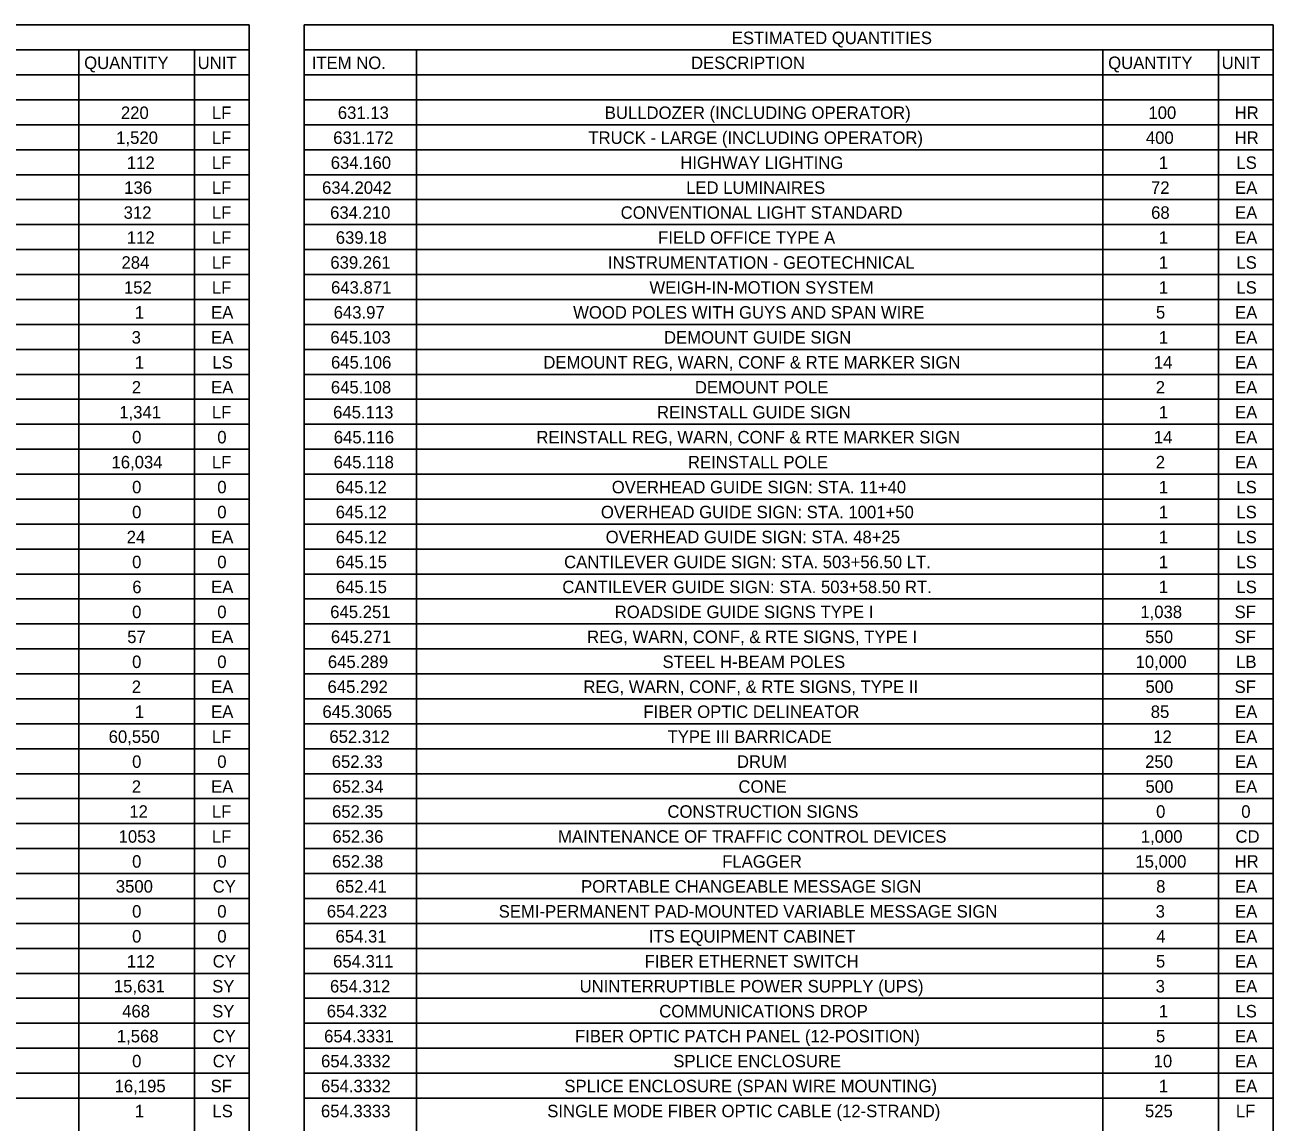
# Model space of a CAD drawing. Extents: x -18.7 to 5.6, y -2.7 to 5.1.
# Drawn here: x 4.632 to 5.617, y 0.886 to 1.751 of the extents above; entities that cross this region are included whole.
import ezdxf

# ---------------------------------------------------------------- set-up
doc = ezdxf.new("R2010")
doc.units = 0
doc.layers.add('ANNOTATION', color=7, linetype='Continuous')
doc.layers.add('BORDER', color=7, linetype='Continuous')

msp = doc.modelspace()

# ---------------------------------------------------------------- linework, layer by layer
at = {"layer": 'BORDER'}
for p, q in [((3.9448, 1.73155), (4.8091, 1.73155)), ((4.67472, 1.73155), (4.67472, 0.01886)), ((4.76611, 1.73155), (4.76611, 0.01886)), ((4.85265, 1.73155), (5.61696, 1.73155)), ((4.94124, 1.73155), (4.94124, 0.01886)), ((5.48258, 1.73155), (5.48258, 0.01886)), ((5.57397, 1.73155), (5.57397, 0.01886)), ((3.9448, 1.71186), (4.8091, 1.71186)), ((4.85265, 1.71186), (5.61696, 1.71186)), ((3.9448, 1.69217), (4.8091, 1.69217)), ((4.85265, 1.69217), (5.61696, 1.69217)), ((3.9448, 1.67249), (4.8091, 1.67249)), ((4.85265, 1.67249), (5.61696, 1.67249)), ((3.9448, 1.6528), (4.8091, 1.6528)), ((4.85265, 1.6528), (5.61696, 1.6528)), ((3.9448, 1.63312), (4.8091, 1.63312)), ((4.85265, 1.63312), (5.61696, 1.63312)), ((3.9448, 1.61343), (4.8091, 1.61343)), ((4.85265, 1.61343), (5.61696, 1.61343)), ((3.9448, 1.59374), (4.8091, 1.59374)), ((4.85265, 1.59374), (5.61696, 1.59374)), ((3.9448, 1.57406), (4.8091, 1.57406)), ((4.85265, 1.57406), (5.61696, 1.57406)), ((3.9448, 1.55437), (4.8091, 1.55437)), ((4.85265, 1.55437), (5.61696, 1.55437)), ((3.9448, 1.53469), (4.8091, 1.53469)), ((4.85265, 1.53469), (5.61696, 1.53469)), ((3.9448, 1.515), (4.8091, 1.515)), ((4.85265, 1.515), (5.61696, 1.515)), ((3.9448, 1.49531), (4.8091, 1.49531)), ((4.85265, 1.49531), (5.61696, 1.49531)), ((3.9448, 1.47563), (4.8091, 1.47563)), ((4.85265, 1.47563), (5.61696, 1.47563)), ((3.9448, 1.45594), (4.8091, 1.45594)), ((4.85265, 1.45594), (5.61696, 1.45594)), ((3.9448, 1.43626), (4.8091, 1.43626)), ((4.85265, 1.43626), (5.61696, 1.43626)), ((3.9448, 1.41657), (4.8091, 1.41657)), ((4.85265, 1.41657), (5.61696, 1.41657)), ((3.9448, 1.39688), (4.8091, 1.39688)), ((4.85265, 1.39688), (5.61696, 1.39688)), ((3.9448, 1.3772), (4.8091, 1.3772)), ((4.85265, 1.3772), (5.61696, 1.3772)), ((3.9448, 1.35751), (4.8091, 1.35751)), ((4.85265, 1.35751), (5.61696, 1.35751)), ((3.9448, 1.33783), (4.8091, 1.33783)), ((4.85265, 1.33783), (5.61696, 1.33783)), ((3.9448, 1.31814), (4.8091, 1.31814)), ((4.85265, 1.31814), (5.61696, 1.31814)), ((3.9448, 1.29845), (4.8091, 1.29845)), ((4.85265, 1.29845), (5.61696, 1.29845)), ((3.9448, 1.27877), (4.8091, 1.27877)), ((4.85265, 1.27877), (5.61696, 1.27877)), ((3.9448, 1.25908), (4.8091, 1.25908)), ((4.85265, 1.25908), (5.61696, 1.25908)), ((3.9448, 1.2394), (4.8091, 1.2394)), ((4.85265, 1.2394), (5.61696, 1.2394)), ((3.9448, 1.21971), (4.8091, 1.21971)), ((4.85265, 1.21971), (5.61696, 1.21971)), ((3.9448, 1.20002), (4.8091, 1.20002)), ((4.85265, 1.20002), (5.61696, 1.20002)), ((3.9448, 1.18034), (4.8091, 1.18034)), ((4.85265, 1.18034), (5.61696, 1.18034)), ((3.9448, 1.16065), (4.8091, 1.16065)), ((4.85265, 1.16065), (5.61696, 1.16065)), ((3.9448, 1.14097), (4.8091, 1.14097)), ((4.85265, 1.14097), (5.61696, 1.14097)), ((3.9448, 1.12128), (4.8091, 1.12128)), ((4.85265, 1.12128), (5.61696, 1.12128)), ((3.9448, 1.10159), (4.8091, 1.10159)), ((4.85265, 1.10159), (5.61696, 1.10159)), ((3.9448, 1.08191), (4.8091, 1.08191)), ((4.85265, 1.08191), (5.61696, 1.08191)), ((3.9448, 1.06222), (4.8091, 1.06222)), ((4.85265, 1.06222), (5.61696, 1.06222)), ((3.9448, 1.04254), (4.8091, 1.04254)), ((4.85265, 1.04254), (5.61696, 1.04254)), ((3.9448, 1.02285), (4.8091, 1.02285)), ((4.85265, 1.02285), (5.61696, 1.02285)), ((3.9448, 1.00316), (4.8091, 1.00316)), ((4.85265, 1.00316), (5.61696, 1.00316)), ((3.9448, 0.98348), (4.8091, 0.98348)), ((4.85265, 0.98348), (5.61696, 0.98348)), ((3.9448, 0.96379), (4.8091, 0.96379)), ((4.85265, 0.96379), (5.61696, 0.96379)), ((3.9448, 0.94411), (4.8091, 0.94411)), ((4.85265, 0.94411), (5.61696, 0.94411)), ((3.9448, 0.92442), (4.8091, 0.92442)), ((4.85265, 0.92442), (5.61696, 0.92442)), ((3.9448, 0.90473), (4.8091, 0.90473)), ((4.85265, 0.90473), (5.61696, 0.90473))]:
    msp.add_line(p, q, dxfattribs=at)
for points in [[(3.9448, 1.75123), (4.8091, 1.75123), (4.8091, 0.01886), (3.9448, 0.01886)], [(4.85265, 1.75123), (5.61696, 1.75123), (5.61696, 0.01886), (4.85265, 0.01886)]]:
    msp.add_lwpolyline(points, close=True, dxfattribs=at)

# ---------------------------------------------------------------- texts
at = {"layer": 'ANNOTATION'}
for s, height, p in [('220', 0.009843, (4.70801, 1.67708)), ('LF', 0.009843, (4.77978, 1.67708)), ('631.13', 0.009843, (4.87914, 1.67708)), ('BULLDOZER (INCLUDING OPERATOR)', 0.009843, (5.08976, 1.67708)), ('100', 0.009843, (5.51865, 1.67708)), ('HR', 0.009843, (5.58665, 1.67708)), ('1,520', 0.009843, (4.70429, 1.6574)), ('LF', 0.009843, (4.77978, 1.6574)), ('631.172', 0.009843, (4.8755, 1.6574)), ('TRUCK - LARGE (INCLUDING OPERATOR)', 0.009843, (5.0768, 1.6574)), ('400', 0.009843, (5.51664, 1.6574)), ('HR', 0.009843, (5.58665, 1.6574)), ('112', 0.009843, (4.7127, 1.63771)), ('LF', 0.009843, (4.77978, 1.63771)), ('634.160', 0.009843, (4.87353, 1.63771)), ('HIGHWAY LIGHTING', 0.009843, (5.14929, 1.63771)), ('1', 0.00984, (5.52687, 1.63771)), ('LS', 0.009843, (5.58806, 1.63771)), ('136', 0.009843, (4.71057, 1.61803)), ('LF', 0.009843, (4.77978, 1.61803)), ('634.2042', 0.009843, (4.86667, 1.61803)), ('LED LUMINAIRES', 0.009843, (5.15393, 1.61803)), ('72', 0.009843, (5.5207, 1.61803)), ('EA', 0.009843, (5.58701, 1.61803)), ('312', 0.009843, (4.71014, 1.59834)), ('LF', 0.009843, (4.77978, 1.59834)), ('634.210', 0.009843, (4.87306, 1.59834)), ('CONVENTIONAL LIGHT STANDARD', 0.009843, (5.10228, 1.59834)), ('68', 0.009843, (5.52078, 1.59834)), ('EA', 0.009843, (5.58701, 1.59834)), ('112', 0.009843, (4.7127, 1.57865)), ('LF', 0.009843, (4.77978, 1.57865)), ('639.18', 0.009843, (4.87752, 1.57865)), ('FIELD OFFICE TYPE A', 0.009843, (5.13182, 1.57865)), ('1', 0.00984, (5.52687, 1.57865)), ('EA', 0.009843, (5.58701, 1.57865)), ('284', 0.009843, (4.70847, 1.55897)), ('LF', 0.009843, (4.77978, 1.55897)), ('639.261', 0.009843, (4.87322, 1.55897)), ('INSTRUMENTATION - GEOTECHNICAL', 0.009843, (5.0922, 1.55897)), ('1', 0.00984, (5.52687, 1.55897)), ('LS', 0.009843, (5.58806, 1.55897)), ('152', 0.009843, (4.71037, 1.53928)), ('LF', 0.009843, (4.77978, 1.53928)), ('643.871', 0.009843, (4.87376, 1.53928)), ('WEIGH-IN-MOTION SYSTEM', 0.009843, (5.12498, 1.53928)), ('1', 0.00984, (5.52687, 1.53928)), ('LS', 0.009843, (5.58806, 1.53928)), ('1', 0.00984, (4.71901, 1.5196)), ('EA', 0.009843, (4.77916, 1.5196)), ('643.97', 0.009843, (4.87585, 1.5196)), ('WOOD POLES WITH GUYS AND SPAN WIRE', 0.009843, (5.06478, 1.5196)), ('5', 0.00984, (5.52458, 1.5196)), ('EA', 0.009843, (5.58701, 1.5196)), ('3', 0.00984, (4.71649, 1.49991)), ('EA', 0.009843, (4.77916, 1.49991)), ('645.103', 0.009843, (4.87325, 1.49991)), ('DEMOUNT GUIDE SIGN', 0.009843, (5.13644, 1.49991)), ('1', 0.00984, (5.52687, 1.49991)), ('EA', 0.009843, (5.58701, 1.49991)), ('1', 0.00984, (4.71901, 1.48022)), ('LS', 0.009843, (4.78021, 1.48022)), ('645.106', 0.009843, (4.87376, 1.48022)), ('DEMOUNT REG, WARN, CONF & RTE MARKER SIGN', 0.009843, (5.04127, 1.48022)), ('14', 0.009843, (5.52292, 1.48022)), ('EA', 0.009843, (5.58701, 1.48022)), ('2', 0.00984, (4.71657, 1.46054)), ('EA', 0.009843, (4.77916, 1.46054)), ('645.108', 0.009843, (4.87364, 1.46054)), ('DEMOUNT POLE', 0.009843, (5.1608, 1.46054)), ('2', 0.00984, (5.52442, 1.46054)), ('EA', 0.009843, (5.58701, 1.46054)), ('1,341', 0.009843, (4.7067, 1.44085)), ('LF', 0.009843, (4.77978, 1.44085)), ('645.113', 0.009843, (4.87542, 1.44085)), ('REINSTALL GUIDE SIGN', 0.009843, (5.13098, 1.44085)), ('1', 0.00984, (5.52687, 1.44085)), ('EA', 0.009843, (5.58701, 1.44085)), ('0', 0.00984, (4.71684, 1.42117)), ('0', 0.00984, (4.78404, 1.42117)), ('645.116', 0.009843, (4.87593, 1.42117)), ('REINSTALL REG, WARN, CONF & RTE MARKER SIGN', 0.009843, (5.03581, 1.42117)), ('14', 0.009843, (5.52292, 1.42117)), ('EA', 0.009843, (5.58701, 1.42117)), ('16,034', 0.009843, (4.70058, 1.40148)), ('LF', 0.009843, (4.77978, 1.40148)), ('645.118', 0.009843, (4.87581, 1.40148)), ('REINSTALL POLE', 0.009843, (5.15534, 1.40148)), ('2', 0.00984, (5.52442, 1.40148)), ('EA', 0.009843, (5.58701, 1.40148)), ('0', 0.00984, (4.71684, 1.38179)), ('0', 0.00984, (4.78404, 1.38179)), ('645.12', 0.009843, (4.87744, 1.38179)), ('OVERHEAD GUIDE SIGN: STA. 11+40', 0.009843, (5.09522, 1.38179)), ('1', 0.00984, (5.52687, 1.38179)), ('LS', 0.009843, (5.58806, 1.38179)), ('0', 0.00984, (4.71684, 1.36211)), ('0', 0.00984, (4.78404, 1.36211)), ('645.12', 0.009843, (4.87744, 1.36211)), ('OVERHEAD GUIDE SIGN: STA. 1001+50', 0.009843, (5.08669, 1.36211)), ('1', 0.00984, (5.52687, 1.36211)), ('LS', 0.009843, (5.58806, 1.36211)), ('24', 0.009843, (4.71258, 1.34242)), ('EA', 0.009843, (4.77916, 1.34242)), ('645.12', 0.009843, (4.87744, 1.34242)), ('OVERHEAD GUIDE SIGN: STA. 48+25', 0.009843, (5.09045, 1.34242)), ('1', 0.00984, (5.52687, 1.34242)), ('LS', 0.009843, (5.58806, 1.34242)), ('0', 0.00984, (4.71684, 1.32274)), ('0', 0.00984, (4.78404, 1.32274)), ('645.15', 0.009843, (4.87759, 1.32274)), ('CANTILEVER GUIDE SIGN: STA. 503+56.50 LT.', 0.009843, (5.05766, 1.32274)), ('1', 0.00984, (5.52687, 1.32274)), ('LS', 0.009843, (5.58806, 1.32274)), ('6', 0.00984, (4.71699, 1.30305)), ('EA', 0.009843, (4.77916, 1.30305)), ('645.15', 0.009843, (4.87759, 1.30305)), ('CANTILEVER GUIDE SIGN: STA. 503+58.50 RT.', 0.009843, (5.05626, 1.30305)), ('1', 0.00984, (5.52687, 1.30305)), ('LS', 0.009843, (5.58806, 1.30305)), ('0', 0.00984, (4.71684, 1.28336)), ('0', 0.00984, (4.78404, 1.28336)), ('645.251', 0.009843, (4.87314, 1.28336)), ('ROADSIDE GUIDE SIGNS TYPE I ', 0.009843, (5.0976, 1.28336)), ('1,038', 0.009843, (5.51227, 1.28336)), ('SF', 0.009843, (5.58663, 1.28336)), ('57', 0.009843, (4.71297, 1.26368)), ('EA', 0.009843, (4.77916, 1.26368)), ('645.271', 0.009843, (4.87368, 1.26368)), ('REG, WARN, CONF, & RTE SIGNS, TYPE I', 0.009843, (5.07581, 1.26368)), ('550', 0.009843, (5.51617, 1.26368)), ('SF', 0.009843, (5.58663, 1.26368)), ('0', 0.00984, (4.71684, 1.24399)), ('0', 0.00984, (4.78404, 1.24399)), ('645.289', 0.009843, (4.87128, 1.24399)), ('STEEL H-BEAM POLES', 0.009843, (5.1353, 1.24399)), ('10,000', 0.009843, (5.50851, 1.24399)), ('LB', 0.009843, (5.58783, 1.24399)), ('2', 0.00984, (4.71657, 1.22431)), ('EA', 0.009843, (4.77916, 1.22431)), ('645.292', 0.009843, (4.87101, 1.22431)), ('REG, WARN, CONF, & RTE SIGNS, TYPE II', 0.009843, (5.07289, 1.22431)), ('500', 0.009843, (5.51633, 1.22431)), ('SF', 0.009843, (5.58663, 1.22431)), ('1', 0.00984, (4.71901, 1.20462)), ('EA', 0.009843, (4.77916, 1.20462)), ('645.3065', 0.009843, (4.86698, 1.20462)), ('FIBER OPTIC DELINEATOR', 0.009843, (5.12024, 1.20462)), ('85', 0.009843, (5.52047, 1.20462)), ('EA', 0.009843, (5.58701, 1.20462)), ('60,550', 0.009843, (4.69833, 1.18493)), ('LF', 0.009843, (4.77978, 1.18493)), ('652.312', 0.009843, (4.87248, 1.18493)), ('TYPE III BARRICADE', 0.009843, (5.13927, 1.18493)), ('12', 0.009843, (5.52249, 1.18493)), ('EA', 0.009843, (5.58701, 1.18493)), ('0', 0.00984, (4.71684, 1.16525)), ('0', 0.00984, (4.78404, 1.16525)), ('652.33', 0.009843, (4.87434, 1.16525)), ('DRUM', 0.009843, (5.19401, 1.16525)), ('250', 0.009843, (5.51602, 1.16525)), ('EA', 0.009843, (5.58701, 1.16525)), ('2', 0.00984, (4.71657, 1.14556)), ('EA', 0.009843, (4.77916, 1.14556)), ('652.34', 0.009843, (4.87484, 1.14556)), ('CONE', 0.009843, (5.19524, 1.14556)), ('500', 0.009843, (5.51633, 1.14556)), ('EA', 0.009843, (5.58701, 1.14556)), ('12', 0.009843, (4.71463, 1.12588)), ('LF', 0.009843, (4.77978, 1.12588)), ('652.35', 0.009843, (4.87457, 1.12588)), ('CONSTRUCTION SIGNS', 0.009843, (5.13917, 1.12588)), ('0', 0.00984, (5.5247, 1.12588)), ('0', 0.00984, (5.5919, 1.12588)), ('1053', 0.009843, (4.70619, 1.10619)), ('LF', 0.009843, (4.77978, 1.10619)), ('652.36', 0.009843, (4.87484, 1.10619)), ('MAINTENANCE OF TRAFFIC CONTROL DEVICES', 0.009843, (5.05289, 1.10619)), ('1,000', 0.009843, (5.51262, 1.10619)), ('CD', 0.009843, (5.58733, 1.10619)), ('0', 0.00984, (4.71684, 1.0865)), ('0', 0.00984, (4.78404, 1.0865)), ('652.38', 0.009843, (4.87472, 1.0865)), ('FLAGGER', 0.009843, (5.18237, 1.0865)), ('15,000', 0.009843, (5.50835, 1.0865)), ('HR', 0.009843, (5.58665, 1.0865)), ('3500', 0.009843, (4.70398, 1.06682)), ('CY', 0.009843, (4.7804, 1.06682)), ('652.41', 0.009843, (4.8774, 1.06682)), ('PORTABLE CHANGEABLE MESSAGE SIGN', 0.009843, (5.07106, 1.06682)), ('8', 0.00984, (5.52474, 1.06682)), ('EA', 0.009843, (5.58701, 1.06682)), ('0', 0.00984, (4.71684, 1.04713)), ('0', 0.00984, (4.78404, 1.04713)), ('654.223', 0.009843, (4.87046, 1.04713)), ('SEMI-PERMANENT PAD-MOUNTED VARIABLE MESSAGE SIGN', 0.009843, (5.00605, 1.04713)), ('3', 0.00984, (5.52435, 1.04713)), ('EA', 0.009843, (5.58701, 1.04713)), ('0', 0.00984, (4.71684, 1.02745)), ('0', 0.00984, (4.78404, 1.02745)), ('654.31', 0.009843, (4.87732, 1.02745)), ('ITS EQUIPMENT CABINET', 0.009843, (5.12449, 1.02745)), ('4', 0.00984, (5.52485, 1.02745)), ('EA', 0.009843, (5.58701, 1.02745)), ('112', 0.009843, (4.7127, 1.00776)), ('CY', 0.009843, (4.7804, 1.00776)), ('654.311', 0.009843, (4.87539, 1.00776)), ('FIBER ETHERNET SWITCH', 0.009843, (5.12116, 1.00776)), ('5', 0.00984, (5.52458, 1.00776)), ('EA', 0.009843, (5.58701, 1.00776)), ('15,631', 0.009843, (4.70244, 0.98807)), ('SY', 0.009843, (4.78001, 0.98807)), ('654.312', 0.009843, (4.87294, 0.98807)), ('UNINTERRUPTIBLE POWER SUPPLY (UPS)', 0.009843, (5.0699, 0.98807)), ('3', 0.00984, (5.52435, 0.98807)), ('EA', 0.009843, (5.58701, 0.98807)), ('468', 0.009843, (4.70898, 0.96839)), ('SY', 0.009843, (4.78001, 0.96839)), ('654.332', 0.009843, (4.87039, 0.96839)), ('COMMUNICATIONS DROP', 0.009843, (5.13272, 0.96839)), ('1', 0.00984, (5.52687, 0.96839)), ('LS', 0.009843, (5.58806, 0.96839)), ('1,568', 0.009843, (4.7048, 0.9487)), ('CY', 0.009843, (4.7804, 0.9487)), ('654.3331', 0.009843, (4.86834, 0.9487)), ('FIBER OPTIC PATCH PANEL (12-POSITION)', 0.009843, (5.06628, 0.9487)), ('5', 0.00984, (5.52458, 0.9487)), ('EA', 0.009843, (5.58701, 0.9487)), ('0', 0.00984, (4.71684, 0.92902)), ('CY', 0.009843, (4.7804, 0.92902)), ('654.3332', 0.009843, (4.86589, 0.92902)), ('SPLICE ENCLOSURE', 0.009843, (5.14382, 0.92902)), ('10', 0.009843, (5.52276, 0.92902)), ('EA', 0.009843, (5.58701, 0.92902)), ('16,195', 0.009843, (4.70302, 0.90933)), ('SF', 0.009843, (4.77877, 0.90933)), ('654.3332', 0.009843, (4.86589, 0.90933)), ('SPLICE ENCLOSURE (SPAN WIRE MOUNTING)', 0.009843, (5.05787, 0.90933)), ('1', 0.00984, (5.52687, 0.90933)), ('EA', 0.009843, (5.58701, 0.90933)), ('1', 0.00984, (4.71901, 0.88964)), ('LS', 0.009843, (4.78021, 0.88964)), ('654.3333', 0.009843, (4.86582, 0.88964)), ('SINGLE MODE FIBER OPTIC CABLE (12-STRAND)', 0.009843, (5.04436, 0.88964)), ('525', 0.009843, (5.5159, 0.88964)), ('LF', 0.009843, (5.58764, 0.88964))]:
    msp.add_text(s, height=height, dxfattribs=at).set_placement(p)
at = {"layer": 'BORDER'}
for s, height, p in [('ESTIMATED QUANTITIES', 0.0098425, (5.18993, 1.73614)), ('QUANTITY', 0.009843, (4.67903, 1.71646)), ('UNIT', 0.009843, (4.76854, 1.71646)), ('ITEM NO.', 0.009843, (4.85856, 1.71646)), ('DESCRIPTION', 0.0098425, (5.15777, 1.71646)), ('QUANTITY', 0.009843, (5.48689, 1.71646)), ('UNIT', 0.009843, (5.5764, 1.71646))]:
    msp.add_text(s, height=height, dxfattribs=at).set_placement(p)

doc.saveas('drawing.dxf')
